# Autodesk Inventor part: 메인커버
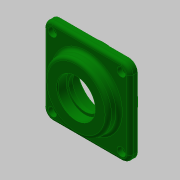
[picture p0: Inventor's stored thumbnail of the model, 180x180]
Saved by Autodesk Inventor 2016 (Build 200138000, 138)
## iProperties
Created: 2018-09
Part Number: 메인커버
Material: 알루미늄 6061
Document SubType Name: Modeling
Designer: mduedu
Density: 2.71 g/cm^3
Appearance: 진녹색
Mass: 178.463 g
Surface Area: 197.883 cm^2
Volume: 65.8536 cm^3
Author: mduedu
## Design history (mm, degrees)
sketch "스케치1"
  geometry: L1 (-40, -40)-(40, -40); L2 (40, -40)-(40, 40); L3 (40, 40)-(-40, 40); L4 (-40, 40)-(-40, -40); L5 (-40, -40)-(40, 40); L6 (40, -40)-(-40, 40); 1 further point
  constraints: 12 end point, 2 midpoint, 2 parallel, 1 horizontal, 1 perpendicular
  dimensions: "d0" = 80 distance of L3.end L2.end; "d1" = 80 distance of L2.end L1.end
extrude "돌출1" new body sketch "스케치1" distance "d2" = 7; taper "d3" = 0 deg
sketch "스케치2"
  geometry: C1 r 30 at (0, 0); 1 further point
  constraints: 1 centre point, 1 coincident
  dimensions: "d4" = 60 diameter of C1
extrude "돌출2" join sketch "스케치2" distance "d5" = 10; taper "d6" = 0 deg
sketch "스케치3"
  geometry: C1 r 32.5 at (0, 0); 1 further point
  constraints: 1 centre point, 1 coincident
  dimensions: "d7" = 65 diameter of C1
extrude "돌출3" join sketch "스케치3" distance "d8" = 9; taper "d9" = 0 deg
sketch "스케치4"
  geometry: L1 (-32.5, -9)-(32.5, -9) reference; L2 (30, 17)-(-30, 17) reference; L3 (0, 17)-(0, -9); L4 (0, -9)-(23.5, -9); L5 (23.5, -9)-(23.5, 5); L6 (23.5, 5)-(0, 5); L7 (0, 5)-(0, -9); L8 (0, 5)-(15, 5); L9 (15, 5)-(15, 8.7); L10 (15, 8.7)-(0, 8.7); L11 (0, 8.7)-(0, 5); L12 (0, 8.7)-(17.5, 8.7); L13 (17.5, 8.7)-(17.5, 17); L14 (17.5, 17)-(0, 17); L15 (0, 17)-(0, 8.7); 1 further point
  constraints: 26 end point, 6 parallel, 3 horizontal, 3 perpendicular, 2 midpoint, 1 point on line
  dimensions: "d10" = 14 distance of L4.end L5.end; "d12" = 8.3 distance of L12.end L13.end; "d13" = 35 diameter of L13 L3; "d14" = 30 diameter of L9 L3; "d15" = 47 diameter of L5 L3
revolve "회전1" sketch "스케치4" stored, may be unused: angle "d16" = 90 deg
fillet "모깎기1" dims "d17" = 8
fillet "모깎기2" dims "d18" = 3
fillet "모깎기3" dims "d19" = 3
chamfer "모따기1" distance "d20" = 0.8; stored, may be unused: second distance "d21" = 2, angle "d22" = 30 deg
chamfer "모따기2" distance "d23" = 1; stored, may be unused: second distance "d24" = 2, angle "d25" = 30 deg
fillet "모깎기4" dims "d26" = 0.3
sketch "스케치5"
  geometry: A1 r 8 centre (-32, 32) between (-32, 40) and (-40, 32) reference; A2 r 8 centre (-32, -32) between (-40, -32) and (-32, -40) reference; A3 r 8 centre (32, -32) between (32, -40) and (40, -32) reference; A4 r 8 centre (32, 32) between (40, 32) and (32, 40) reference; 5 further points
  constraints: 4 coincident
hole "구멍1" sketch "스케치5" at (-32, 32), (32, 32), (32, -32), (-32, -32) diameter "d27" = 4.5; stored, may be unused: countersink angle "d31" = 90 deg, drill point angle "d33" = 118 deg; dims "d28" = 6, "d29" = 8, "d30" = 4.4, "d32" = 8
node "솔리드1"
